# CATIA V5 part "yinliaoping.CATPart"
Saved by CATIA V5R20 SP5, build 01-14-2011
Part number: 饮料瓶
Material "DS Light Blue": density 7860 kg/m3, Young's modulus 2e+11 Pa, Poisson ratio 0.266
Bounding box of the stored display mesh (mm): x -25 to 25.2, y -25 to 344.945, z 0 to 308.123
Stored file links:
  E:\180211214wjl\yinliaoping.CATPart
  C:\Program Files\Dassault Systemes\B20\intel_a\startup\materials\Catalog.CATMaterial
  C:\Program Files\Dassault Systemes\B20\intel_a\startup\materials\blue_env_512x512.jpg
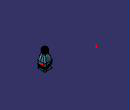
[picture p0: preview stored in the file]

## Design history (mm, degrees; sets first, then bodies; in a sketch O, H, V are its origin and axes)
Set1
  Sketch1 on xy-plane, origin (0, 0, 0), H (1, 0, 0), V (0, 1, 0)
    line L1 (25, 25) -> (25, -25)
    line L2 (25, -25) -> (-25, -25)
    line L3 (-25, -25) -> (-25, 25)
    line L4 (-25, 25) -> (25, 25)
    length L4 = 50
    length L1 = 50
    vertical: L1 V, L3 V
    horizontal: L2 H, L4 H
    equidistance: L1 L3 O, L2 L4 O
  Sketch2 on face of Pad1 from Sketch1.L2, origin (0, -25, 0), H (1, 0, 0), V (0, 0, 1)
    spline S1 through (-40, 20) (-10, 30) (10, 20) (40, 30)
  Extrude1: Element1 Sketch2, Lim1 52, Lim2 52
  MultiSel1: CommonCtxFeats ({extract ExtractElem face of Pad1 from Sketch1.L2}; {extract ExtractElem face of Pad1 from Sketch1.L1}; {extract ExtractElem face of Pad1 from Sketch1.L4}; {extract ExtractElem face of Fillet1}; {extract ExtractElem edge [face of Fillet1 | face of Pad1 from Sketch1.L4]}; {extract ExtractElem face of Fillet1}; {extract ExtractElem face of Fillet1}; {extract ExtractElem face of Pad1 from Sketch1.L3}; {extract ExtractElem face of Fillet1})
  Join1: Elements ({intersect ToIntersect1 {extract ExtractElem face of Pad1 from Sketch1.L2}, ToIntersect2 Extrude1}; {intersect ToIntersect1 {extract ExtractElem face of Pad1 from Sketch1.L4}, ToIntersect2 Extrude1}; {intersect ToIntersect1 {extract ExtractElem face of Fillet1}, ToIntersect2 Extrude1}; {intersect ToIntersect1 {extract ExtractElem face of Fillet1}, ToIntersect2 Extrude1}; {intersect ToIntersect1 {extract ExtractElem face of Pad1 from Sketch1.L1}, ToIntersect2 Extrude1}; {intersect ToIntersect1 {extract ExtractElem face of Fillet1}, ToIntersect2 Extrude1}; {intersect ToIntersect1 {extract ExtractElem face of Fillet1}, ToIntersect2 Extrude1}; {intersect ToIntersect1 {extract ExtractElem face of Pad1 from Sketch1.L3}, ToIntersect2 Extrude1})
  Sketch3 on face of Pad1 from Sketch1.L2, origin (0, -25, 0), H (1, 0, 0), V (0, 0, 1)
    spline S1 through (-30, 40) (-10, 40) (10, 30) (30, 30)
  Extrude2: Element1 Sketch3, Lim1 52, Lim2 52
  MultiSel2: CommonCtxFeats ({extract ExtractElem face of Pad1 from Sketch1.L2}; {extract ExtractElem face of Fillet1}; {extract ExtractElem face of Pad1 from Sketch1.L3}; {extract ExtractElem face of Fillet1}; {extract ExtractElem face of Pad1 from Sketch1.L1}; {extract ExtractElem face of Fillet1}; {extract ExtractElem face of Pad1 from Sketch1.L4}; {extract ExtractElem face of Fillet1})
  Join2: Elements ({intersect ToIntersect1 {extract ExtractElem face of Fillet1}, ToIntersect2 Extrude2}; {intersect ToIntersect1 {extract ExtractElem face of Pad1 from Sketch1.L3}, ToIntersect2 Extrude2}; {intersect ToIntersect1 {extract ExtractElem face of Fillet1}, ToIntersect2 Extrude2}; {intersect ToIntersect1 {extract ExtractElem face of Pad1 from Sketch1.L4}, ToIntersect2 Extrude2}; {intersect ToIntersect1 {extract ExtractElem face of Pad1 from Sketch1.L1}, ToIntersect2 Extrude2}; {intersect ToIntersect1 {extract ExtractElem face of Fillet1}, ToIntersect2 Extrude2}; {intersect ToIntersect1 {extract ExtractElem face of Fillet1}, ToIntersect2 Extrude2}; {intersect ToIntersect1 {extract ExtractElem face of Pad1 from Sketch1.L2}, ToIntersect2 Extrude2})
  Plane1: type Normal, Curve Join1, RefPoint vertex [face of MultiSel1 | face of MultiSel1]
  Sketch4 on Plane1, origin (-19.567, 0, 5.3284), H (0, 1, 0), V (0.2627, 0, 0.9649)
    circle A1 centre (-24.8299, 26.6303) radius 2
    radius A1 = 2
Body1 (main body), material "DS Light Blue"
  Pad1: profile Sketch1, direction (0, 0, 1), length 50
  Fillet1: on edge [face of Pad1 from Sketch1.L4 | face of Pad1 from Sketch1.L1]; edge [face of Pad1 from Sketch1.L1 | face of Pad1 from Sketch1.L2]; edge [face of Pad1 from Sketch1.L2 | face of Pad1 from Sketch1.L3]; edge [face of Pad1 from Sketch1.L3 | face of Pad1 from Sketch1.L4]
  Fillet2: radius 8, on start face of Pad1
  Plane2: type Offset, RefPlane end face of Pad1, Offset 40, reversed
  Sketch5 on Plane2, origin (0, 0, 90), H (1, 0, 0), V (0, -1, 0)
    circle A1 centre (0, 0) radius 15
    radius A1 = 15
  Pad2: profile Sketch5, direction (0, 0, 1), length 20
  Sketch6 on end face of Pad1, origin (0, 0, 50), H (1, 0, 0), V (0, 1, 0)
    point P1 (25, 0)
    distance P1 V = 25
  Sketch7 on start face of Pad2, origin (0, 0, 90), H (1, 0, 0), V (0, -1, 0)
    point P1 (15, 0)
    distance P1 V = 15
  Loft1: solid, Sections ({boundary Boundary {extract ExtractElem end face of Pad1}}; {boundary Boundary {extract ExtractElem start face of Pad2}}), StartFace end face of Pad1, EndFace start face of Pad2
  Slot1: profile Sketch4, centre curve Join1
  Plane3: type Normal, Curve Join2, RefPoint vertex [face of MultiSel2 | face of MultiSel2]
  Sketch8 on Plane3, origin (4.7043, 0, -1.258), H (0, -1, 0), V (0.2583, 0, 0.9661)
    circle A1 centre (-25.0087, 31.3379) radius 2
    radius A1 = 2
  Slot2: profile Sketch8, centre curve Join2
  Shell1: ExtOffset 0, Face end face of Pad2, IntOffset 1
  Plane4: type Offset, RefPlane Plane2, Offset 2, reversed
  Sketch9 on Plane4, origin (0, 0, 92), H (1, 0, 0), V (0, -1, 0)
    point P1 (15, 0)
    distance P1 V = 15
    coincidence: P1 H
  Helix1: Direction Z axis, RefPoint Sketch9, Pitch 3, Height 16, TaperAngle 0
  Point1: type OnCurve, Support Helix1, RefPoint vertex of Helix1, Length -5
  Point2: type OnCurve, Support Helix1, Length 5.216
  Line1: type PtDir, RefPoint vertex of Helix1, Direction (0, 1, 0), Start 0, End 5
  Line2: type PtDir, RefPoint Sketch9, Direction (1, 0, 0), Start 0, End 5
  Connect1: Curve1 Helix1, Point1 Point1, Tension1 1, Curve2 Line1, Point2 vertex of Line1, Tension2 1
  Connect2: Curve1 Line2, Point1 vertex of Line2, Tension1 1, Curve2 Connect1, Point2 Point2, Tension2 1
  Plane5: type Normal, Curve Connect2, RefPoint vertex of Connect2
  Sketch10 on Plane5, origin (10, 0, 0), H (0, 1, 0), V (0, 0, 1)
    circle A1 centre (0, 92.1531) radius 1
    point P1 (0, 92.1531)
    radius A1 = 1
    coincidence: P1 V
  Rib1: profile Sketch10, centre curve Connect2
  Body2
    Sketch11 on Plane2, origin (0, 0, 90), H (1, 0, 0), V (0, -1, 0)
      circle A1 centre (0, 0) radius 14
      radius A1 = 14
    Pad3: profile Sketch11, direction (0, 0, 1), length 24
  Remove1: tool Body2
Body3
Body4
  Sketch12 on face of Pad1 from Sketch1.L1, origin (25, 0, 0), H (0, 1, 0), V (0, 0, 1)
    polyline C1
    polyline C2
    polyline C3
    polyline C4
    polyline C5
    polyline C6
    polyline C7
    polyline C8
    polyline C9
    polyline C10
    polyline C11
    polyline C12
    polyline C13
    polyline C14
  Pad4: profile Sketch12, direction (1, 0, 0), length 0.2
